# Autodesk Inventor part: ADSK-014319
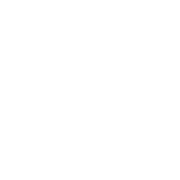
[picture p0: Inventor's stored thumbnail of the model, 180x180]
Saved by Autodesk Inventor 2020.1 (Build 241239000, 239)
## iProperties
Created: 2019-10
Part Number: ADSK-014319
Material: 1.0501 C35
Document SubType Name: Modeling
Designer: lutzd
Density: 7.84 g/cm^3
Appearance: Stahl
VLDS_Profile: Default Part
VLDS_TimeStamp: 2016-07-29
VLDS_FailCnt: 0
VLDS_AcceptCnt: 0
Dimensions: 0x0x0 mm
Mass: 0 kg
DocNumber: ADSK-014319
Folder: 01 - Themengebiete\Simplification\01 - Packaging machine\
VDS_Category: 3D Komponenten
VDS_NumSchm: Autodesk
Title: skeleton
Author: lutzd
Revision Number: -
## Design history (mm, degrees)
sketch "Skizze1"
  geometry: L1 (-280, 0)-(280, 0); L2 (-280, -114)-(-280, 64); L3 (280, -64)-(280, 114); L4 (-202.5, 25)-(202.5, 25); 4 further points
  constraints: 8 end point, 2 coincident, 2 horizontal, 2 midpoint, 2 point on line, 2 vertical, 1 vertical alignment
  dimensions: "d0" = 560 distance of L1.start L1.end; "d1" = 178 distance of L3.start L3.end; "d2" = 178 distance of L2.start L2.end (= d1); "d3" = 114 distance from line of L1 L3.end; "d4" = 114 distance from line of L1 L2.start (= d3); "d5" = 405 distance of L4.start L4.end; "d7" = 25 distance between parallel lines of L1 L4
